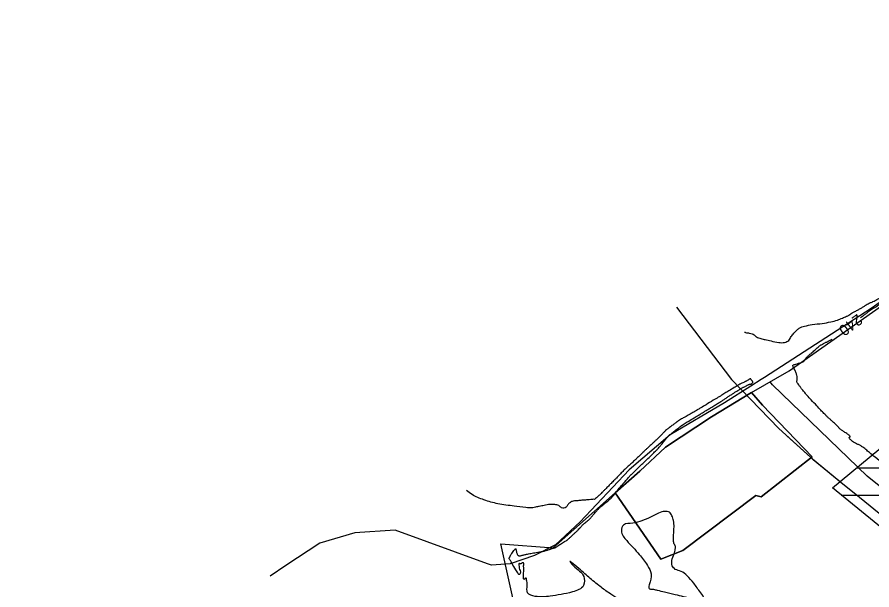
# Model space of a CAD drawing. Extents: x -478464 to -472469, y -1118040 to -1113785.
# Drawn here: x -477315.2 to -477003.6, y -1115098.1 to -1114889.2 of the extents above; entities that cross this region are included whole.
import ezdxf

# ---------------------------------------------------------------- set-up
doc = ezdxf.new("R2010")
doc.units = 0
for name, color, linetype in [('meliorace', 7, 'Continuous'), ('ObPÚ', 7, 'Continuous'), ('silnice', 7, 'Continuous'), ('telekomunikační kabel_O2', 7, 'Continuous'), ('vodní plochy', 7, 'Continuous'), ('Vrstevnice_hlavni', 7, 'Continuous'), ('Vrstevnice_popis', 7, 'Continuous'), ('Vrstevnice_vedlejsi', 7, 'Continuous')]:
    doc.layers.add(name, color=color, linetype=linetype)

msp = doc.modelspace()

# ---------------------------------------------------------------- linework, layer by layer
at = {"layer": 'meliorace'}
for p, q in [((-477009.054, -1115053.499), (-476582.646, -1115053.499)), ((-477014.727, -1115063.499), (-476601.498, -1115063.499))]:
    msp.add_line(p, q, dxfattribs=at)
for points in [[(-477017.961, -1115060.861), (-476936.974, -1114993.925), (-476875.969, -1114949.47), (-476746.767, -1114867.304), (-476662.849, -1114823.347), (-476637.541, -1114817.103), (-476620.225, -1114819.6), (-476613.565, -1114820.849), (-476597.581, -1114814.605), (-476585.593, -1114810.859), (-476574.669, -1114809.36), (-476544.304, -1114813.357), (-476526.985, -1114812.108), (-476492.353, -1114802.118), (-476476.377, -1114797.375), (-476438.008, -1114791.379), (-476414.829, -1114820.6), (-476383.929, -1114845.826), (-476320.786, -1114840.579)], [(-476300.545, -1114963.207), (-476368.477, -1114983.187), (-476385.793, -1114988.182), (-476407.105, -1114989.43), (-476428.417, -1114990.679), (-476466.247, -1114999.171), (-476589.855, -1115056.864), (-476650.329, -1115091.328), (-476713.19, -1115137.026), (-476738.506, -1115158.512), (-476785.126, -1115129.041), (-476863.979, -1115186.483), (-477017.961, -1115060.861)]]:
    msp.add_lwpolyline(points, dxfattribs=at)
at = {"layer": 'ObPÚ'}
for p, q in [((-477047.46, -1115026.08), (-477062.09, -1115034.97)), ((-477043.48, -1115030.71), (-477047.46, -1115026.08)), ((-477072.47, -1115083.76), (-477045.85, -1115063.61))]:
    msp.add_line(p, q, dxfattribs=at)
for points in [[(-477315.25, -1115330.18), (-477231.42, -1115250.62), (-477154.22, -1115173.58), (-477134.18, -1115148.75), (-477133.16, -1115130.26), (-477132.09, -1115111.94), (-477138.91, -1115081.32), (-477119.74, -1115082.72), (-477097.23, -1115062.71), (-477080.55, -1115086.81), (-477072.47, -1115083.76), (-477045.85, -1115063.61), (-477043.93, -1115064.09), (-477025.31, -1115049.55), (-477043.48, -1115030.71), (-477047.46, -1115026.08), (-477033.7, -1115018.17), (-476933.96, -1114947.92), (-476834.35, -1114877.76), (-476714.64, -1114803.8), (-476602.93, -1114745.91), (-476491.34, -1114705.52), (-476390.17, -1114678.77), (-476300.68, -1114655.71)], [(-477047.46, -1115026.08), (-477043.48, -1115030.71), (-477025.31, -1115049.55), (-477043.93, -1115064.09), (-477045.85, -1115063.61), (-477072.47, -1115083.76), (-477080.55, -1115086.81), (-477097.23, -1115062.71), (-477088.23, -1115054.79), (-477078.85, -1115045.98), (-477062.09, -1115034.97), (-477047.46, -1115026.08)], [(-477045.85, -1115063.61), (-477043.93, -1115064.09), (-477025.31, -1115049.55), (-477043.48, -1115030.71)], [(-477062.09, -1115034.97), (-477078.85, -1115045.98), (-477088.23, -1115054.79), (-477097.23, -1115062.71), (-477080.55, -1115086.81), (-477072.47, -1115083.76)]]:
    msp.add_lwpolyline(points, dxfattribs=at)
at = {"layer": 'silnice'}
msp.add_lwpolyline([(-476261.922, -1115907.288), (-476366.595, -1115823.727), (-476390.845, -1115803.24), (-476425.665, -1115718.481), (-476494.983, -1115557.356), (-476524.795, -1115496.42), (-476580.823, -1115418.032), (-476641.911, -1115352.297), (-476741.891, -1115268.259), (-476824.194, -1115202.313), (-477005.33, -1115056.573), (-477039.82, -1115023.276), (-477040.729, -1115022.048)], dxfattribs=at)
at = {"layer": 'telekomunikační kabel_O2'}
msp.add_line((-477011.16, -1115061.79), (-477010.07, -1115062.67), dxfattribs=at)
msp.add_line((-477011.16, -1115061.79), (-477010.07, -1115062.67), dxfattribs=at)
for points in [[(-477074.85, -1114994.92), (-477054.75, -1115021.38), (-477037.48, -1115039.27), (-477026.01, -1115049.69), (-477014.91, -1115058.73)], [(-477034.596, -1115041.89), (-477026.01, -1115049.69), (-477014.91, -1115058.73)], [(-477025.002, -1115050.511), (-477014.91, -1115058.73)], [(-477025.002, -1115050.511), (-477014.91, -1115058.73)], [(-477014.91, -1115058.73), (-477011.16, -1115061.79)], [(-477014.91, -1115058.73), (-477011.16, -1115061.79)], [(-477014.91, -1115058.73), (-477014.596, -1115058.986)], [(-477014.91, -1115058.73), (-477014.596, -1115058.986)], [(-477010.07, -1115062.67), (-476985.91, -1115082.25)]]:
    msp.add_lwpolyline(points, dxfattribs=at)
at = {"layer": 'vodní plochy'}
msp.add_lwpolyline([(-476969.074, -1114970.997), (-477003.853, -1114995.482), (-477042.717, -1115020.667), (-477043.996, -1115021.391), (-477047.718, -1115023.792), (-477057.356, -1115029.838), (-477077.169, -1115041.531), (-477092.092, -1115054.27), (-477110.002, -1115073.251), (-477118.905, -1115081.598), (-477126.545, -1115085.486), (-477135.508, -1115088.514), (-477142.313, -1115089.059), (-477143.75, -1115088.538), (-477177.386, -1115076.347), (-477192.107, -1115077.213), (-477204.809, -1115080.97), (-477217.213, -1115089.231), (-477222.967, -1115093.062)], dxfattribs=at)
at = {"layer": 'Vrstevnice_hlavni'}
for points in [[(-477049.979, -1115004.029), (-477049.673, -1115004.193), (-477048.26, -1115004.404), (-477047.204, -1115004.683), (-477046.505, -1115005.027), (-477046.164, -1115005.438), (-477045.639, -1115005.805), (-477044.929, -1115006.127), (-477044.034, -1115006.405), (-477042.508, -1115006.787), (-477040.351, -1115007.273), (-477037.562, -1115007.863), (-477035.407, -1115007.799), (-477033.886, -1115007.079), (-477033, -1115005.704), (-477032.062, -1115004.503), (-477031.073, -1115003.477), (-477030.034, -1115002.625), (-477028.119, -1115001.907), (-477025.328, -1115001.324), (-477021.663, -1115000.876), (-477018.599, -1115000.325), (-477016.138, -1114999.672), (-477014.278, -1114998.917), (-477012.873, -1114998.304), (-477011.923, -1114997.835), (-477011.428, -1114997.509), (-477010.705, -1114997.08), (-477009.754, -1114996.549), (-477008.574, -1114995.914), (-477007.491, -1114995.299), (-477006.505, -1114994.702), (-477005.616, -1114994.125), (-477004.874, -1114993.69), (-477004.28, -1114993.398), (-477003.833, -1114993.249), (-477003.188, -1114992.955), (-477002.345, -1114992.516), (-477001.305, -1114991.933), (-477000.403, -1114991.481), (-476999.64, -1114991.162), (-476999.016, -1114990.973), (-476998.464, -1114990.728), (-476997.985, -1114990.425), (-476997.579, -1114990.066), (-476997.143, -1114989.765), (-476996.676, -1114989.524), (-476996.178, -1114989.342), (-476995.627, -1114989.011), (-476995.023, -1114988.533), (-476994.365, -1114987.907), (-476993.741, -1114987.384), (-476993.153, -1114986.963), (-476992.599, -1114986.645), (-476992.009, -1114986.355), (-476991.383, -1114986.092), (-476990.719, -1114985.856), (-476990.255, -1114985.689), (-476989.991, -1114985.591), (-476989.925, -1114985.561), (-476989.901, -1114985.553), (-476989.919, -1114985.568), (-476989.977, -1114985.605), (-476990.02, -1114985.633), (-476990.048, -1114985.653), (-476990.061, -1114985.663), (-476990.326, -1114985.857), (-476990.841, -1114986.233), (-476991.608, -1114986.792), (-476992.308, -1114987.388), (-476992.94, -1114988.02), (-476993.504, -1114988.689), (-476994.025, -1114989.245), (-476994.503, -1114989.688), (-476994.937, -1114990.017), (-476995.402, -1114990.301), (-476995.899, -1114990.54), (-476996.428, -1114990.734), (-476996.92, -1114991.026), (-476997.375, -1114991.417), (-476997.795, -1114991.906), (-476998.298, -1114992.365), (-476998.884, -1114992.793), (-476999.553, -1114993.19), (-477000.214, -1114993.61), (-477000.867, -1114994.052), (-477001.512, -1114994.518), (-477002.106, -1114994.907), (-477002.649, -1114995.22), (-477003.142, -1114995.458), (-477003.814, -1114995.885), (-477004.665, -1114996.502)], [(-477004.665, -1114996.502), (-477005.695, -1114997.309), (-477006.489, -1114997.933), (-477007.047, -1114998.372), (-477007.691, -1114998.882)], [(-477017.894, -1115036.673), (-477018.831, -1115035.848), (-477019.673, -1115035.079), (-477020.422, -1115034.367), (-477021.076, -1115033.712), (-477022.168, -1115032.564), (-477023.697, -1115030.923), (-477025.662, -1115028.788), (-477027.122, -1115027.188), (-477028.074, -1115026.123), (-477028.52, -1115025.593), (-477029.034, -1115024.943), (-477029.617, -1115024.173), (-477030.269, -1115023.282), (-477030.708, -1115022.682), (-477030.934, -1115022.374), (-477030.946, -1115022.357), (-477030.928, -1115022.077), (-477030.878, -1115021.535), (-477030.797, -1115020.729), (-477030.934, -1115019.788), (-477031.286, -1115018.713), (-477031.856, -1115017.503), (-477032.238, -1115016.683), (-477032.433, -1115016.253), (-477032.44, -1115016.214), (-477032.443, -1115016.185), (-477032.441, -1115016.166), (-477032.435, -1115016.159), (-477032.431, -1115016.153), (-477032.428, -1115016.149), (-477032.426, -1115016.147), (-477032.373, -1115016.122), (-477032.267, -1115016.074), (-477032.11, -1115016.003), (-477031.64, -1115015.843), (-477030.858, -1115015.596), (-477029.763, -1115015.26), (-477028.959, -1115014.975), (-477028.444, -1115014.74), (-477028.219, -1115014.556), (-477028.06, -1115014.364), (-477027.968, -1115014.165), (-477027.943, -1115013.958), (-477027.674, -1115013.593), (-477027.161, -1115013.071), (-477026.405, -1115012.392), (-477025.889, -1115011.927), (-477025.616, -1115011.677), (-477025.583, -1115011.642), (-477025.534, -1115011.602), (-477025.469, -1115011.556), (-477025.387, -1115011.505), (-477025.033, -1115011.201), (-477024.407, -1115010.643), (-477023.509, -1115009.833), (-477022.858, -1115009.263), (-477022.455, -1115008.935), (-477022.299, -1115008.848), (-477021.991, -1115008.674), (-477021.533, -1115008.413), (-477020.923, -1115008.064), (-477020.468, -1115007.826), (-477020.167, -1115007.697), (-477020.021, -1115007.678), (-477019.883, -1115007.635), (-477019.754, -1115007.567), (-477019.633, -1115007.475), (-477019.398, -1115007.325), (-477019.047, -1115007.117), (-477018.115, -1115006.584)], [(-476873.251, -1115143.677), (-476873.507, -1115142.01), (-476873.554, -1115139.102), (-476873.522, -1115134.12), (-476873.41, -1115127.063), (-476873.808, -1115122.086), (-476874.717, -1115119.19), (-476876.136, -1115118.374), (-476877.354, -1115117.171), (-476878.371, -1115115.579), (-476879.185, -1115113.6), (-476882.364, -1115111.475), (-476887.908, -1115109.205), (-476895.815, -1115106.789), (-476902.242, -1115103.761), (-476907.186, -1115100.12), (-476910.649, -1115095.867), (-476913.66, -1115091.883), (-476916.218, -1115088.167), (-476918.324, -1115084.72), (-476919.725, -1115082.379), (-476920.421, -1115081.145), (-476920.412, -1115081.017), (-476920.426, -1115080.932), (-476920.462, -1115080.891), (-476920.521, -1115080.893), (-476920.576, -1115080.895), (-476920.627, -1115080.896), (-476920.674, -1115080.898), (-476921.736, -1115080.799), (-476923.814, -1115080.599), (-476926.907, -1115080.3), (-476932.302, -1115079.591), (-476940, -1115078.472), (-476950, -1115076.944), (-476957.876, -1115075.006), (-476963.629, -1115072.657), (-476967.259, -1115069.897), (-476970.802, -1115067.892), (-476974.259, -1115066.643), (-476977.631, -1115066.149), (-476980.601, -1115065.341), (-476983.17, -1115064.218), (-476985.338, -1115062.781), (-476986.878, -1115061.747), (-476987.79, -1115061.118), (-476988.074, -1115060.892), (-476988.478, -1115060.587), (-476989.003, -1115060.204), (-476989.648, -1115059.743), (-476990.332, -1115059.246), (-476991.055, -1115058.714), (-476991.817, -1115058.146), (-476992.891, -1115057.395), (-476994.277, -1115056.46), (-476995.976, -1115055.343), (-476997.039, -1115054.593), (-476997.464, -1115054.21), (-476997.254, -1115054.195), (-476998.009, -1115053.437), (-476999.729, -1115051.937), (-477002.416, -1115049.693), (-477004.444, -1115048.001), (-477005.814, -1115046.86), (-477006.527, -1115046.27), (-477007.324, -1115045.723), (-477008.206, -1115045.221), (-477009.173, -1115044.763), (-477009.833, -1115044.445), (-477010.186, -1115044.267), (-477010.232, -1115044.228), (-477010.318, -1115044.158), (-477010.443, -1115044.058), (-477010.608, -1115043.927), (-477010.866, -1115043.703), (-477011.219, -1115043.389), (-477011.666, -1115042.982), (-477011.859, -1115042.654), (-477011.796, -1115042.405), (-477011.479, -1115042.235), (-477011.695, -1115041.846), (-477012.445, -1115041.236), (-477013.729, -1115040.407), (-477014.642, -1115039.799), (-477015.184, -1115039.41), (-477015.355, -1115039.241), (-477015.476, -1115039.117), (-477015.545, -1115039.038), (-477015.564, -1115039.003), (-477015.672, -1115038.875), (-477015.869, -1115038.653), (-477016.157, -1115038.339), (-477016.405, -1115038.07), (-477016.615, -1115037.849), (-477016.786, -1115037.674), (-477017.213, -1115037.282), (-477017.894, -1115036.673)]]:
    msp.add_spline(points, degree=3, dxfattribs=at)
at = {"layer": 'Vrstevnice_vedlejsi'}
for points in [[(-477108.024, -1115073.453), (-477107.41, -1115072.982), (-477106.961, -1115072.629), (-477106.676, -1115072.395), (-477106.556, -1115072.278), (-477106.091, -1115071.757), (-477105.281, -1115070.832), (-477104.126, -1115069.502), (-477103.309, -1115068.574), (-477102.828, -1115068.046), (-477102.685, -1115067.92), (-477102.316, -1115067.626), (-477101.72, -1115067.165), (-477100.898, -1115066.537), (-477100.184, -1115065.97), (-477099.579, -1115065.464), (-477099.081, -1115065.02), (-477098.73, -1115064.701), (-477098.524, -1115064.509), (-477098.465, -1115064.444), (-477098.01, -1115063.889), (-477097.162, -1115062.844), (-477095.919, -1115061.311), (-477094.978, -1115060.158), (-477094.339, -1115059.385), (-477094.002, -1115058.992), (-477093.57, -1115058.494), (-477093.044, -1115057.889), (-477092.423, -1115057.178), (-477091.967, -1115056.663), (-477091.675, -1115056.343), (-477091.547, -1115056.218), (-477091.414, -1115056.093), (-477091.276, -1115055.968), (-477091.133, -1115055.843), (-477090.09, -1115054.841), (-477088.145, -1115052.963), (-477085.299, -1115050.207), (-477083.328, -1115048.299), (-477082.232, -1115047.238), (-477082.012, -1115047.025), (-477081.803, -1115046.81), (-477081.606, -1115046.593), (-477081.422, -1115046.376), (-477080.916, -1115045.76), (-477080.09, -1115044.745), (-477078.942, -1115043.332), (-477078.165, -1115042.381), (-477077.759, -1115041.889), (-477077.722, -1115041.859), (-477077.193, -1115041.444), (-477076.171, -1115040.644), (-477074.656, -1115039.459), (-477073.586, -1115038.623), (-477072.96, -1115038.136), (-477072.779, -1115037.999), (-477071.961, -1115037.49), (-477070.508, -1115036.61), (-477068.419, -1115035.359), (-477066.799, -1115034.381), (-477065.649, -1115033.675), (-477064.968, -1115033.243), (-477064.004, -1115032.647), (-477062.756, -1115031.889), (-477061.226, -1115030.967), (-477059.874, -1115030.136), (-477058.7, -1115029.396), (-477057.706, -1115028.747), (-477056.705, -1115028.092), (-477055.698, -1115027.432), (-477054.685, -1115026.767), (-477053.73, -1115026.157), (-477052.836, -1115025.601), (-477052, -1115025.101), (-477051.326, -1115024.7), (-477050.814, -1115024.399), (-477050.463, -1115024.197), (-477050.058, -1115023.975), (-477049.6, -1115023.733), (-477049.089, -1115023.47), (-477048.739, -1115023.29), (-477048.551, -1115023.192), (-477048.525, -1115023.177), (-477048.392, -1115023.144), (-477048.151, -1115023.091), (-477047.802, -1115023.02), (-477047.557, -1115022.962), (-477047.416, -1115022.917), (-477047.38, -1115022.886), (-477047.304, -1115022.801), (-477047.188, -1115022.663), (-477047.034, -1115022.472), (-477047.024, -1115022.224), (-477047.159, -1115021.92), (-477047.44, -1115021.559), (-477047.642, -1115021.3), (-477047.764, -1115021.143)], [(-477047.764, -1115021.143), (-477047.807, -1115021.087), (-477047.84, -1115021.051), (-477047.862, -1115021.035), (-477047.874, -1115021.038), (-477048.066, -1115021.148), (-477048.439, -1115021.365), (-477048.993, -1115021.689), (-477049.369, -1115021.906), (-477049.566, -1115022.018), (-477049.585, -1115022.024), (-477049.603, -1115022.032), (-477049.62, -1115022.044), (-477049.636, -1115022.059), (-477049.869, -1115022.179), (-477050.319, -1115022.405), (-477050.986, -1115022.735), (-477051.44, -1115022.961), (-477051.68, -1115023.08), (-477051.707, -1115023.094), (-477052.394, -1115023.504), (-477053.742, -1115024.308), (-477055.751, -1115025.507), (-477057.143, -1115026.339), (-477057.916, -1115026.803), (-477058.072, -1115026.899), (-477058.233, -1115027.001), (-477058.398, -1115027.108), (-477058.569, -1115027.221), (-477059.569, -1115027.831), (-477061.399, -1115028.936), (-477064.059, -1115030.537), (-477065.922, -1115031.657), (-477066.987, -1115032.295), (-477067.255, -1115032.451), (-477067.533, -1115032.618), (-477067.822, -1115032.796), (-477068.122, -1115032.984), (-477068.88, -1115033.421), (-477070.096, -1115034.105), (-477071.77, -1115035.038), (-477072.989, -1115035.726), (-477073.751, -1115036.168), (-477074.057, -1115036.365), (-477074.333, -1115036.554), (-477074.579, -1115036.736), (-477074.794, -1115036.91), (-477075.324, -1115037.31), (-477076.168, -1115037.936), (-477077.327, -1115038.79), (-477078.203, -1115039.464), (-477078.798, -1115039.959), (-477079.111, -1115040.275), (-477079.455, -1115040.634), (-477079.831, -1115041.038), (-477080.238, -1115041.485), (-477080.787, -1115042.043), (-477081.476, -1115042.712), (-477082.307, -1115043.493), (-477083.019, -1115044.159), (-477083.61, -1115044.71), (-477084.082, -1115045.147), (-477084.651, -1115045.674), (-477085.315, -1115046.29), (-477086.075, -1115046.995), (-477086.782, -1115047.662), (-477087.437, -1115048.292), (-477088.038, -1115048.885), (-477088.682, -1115049.509), (-477089.369, -1115050.164), (-477090.097, -1115050.851), (-477090.791, -1115051.495), (-477091.451, -1115052.094), (-477092.076, -1115052.649), (-477092.683, -1115053.204), (-477093.273, -1115053.758), (-477093.846, -1115054.312), (-477094.405, -1115054.864), (-477094.949, -1115055.416), (-477095.479, -1115055.966), (-477096.073, -1115056.582), (-477096.731, -1115057.264), (-477097.453, -1115058.011), (-477098.084, -1115058.661), (-477098.627, -1115059.215), (-477099.079, -1115059.673), (-477099.591, -1115060.191), (-477100.163, -1115060.77), (-477100.794, -1115061.411), (-477101.243, -1115061.866), (-477101.509, -1115062.137), (-477101.593, -1115062.222), (-477101.981, -1115062.587), (-477102.673, -1115063.234), (-477103.67, -1115064.162), (-477104.352, -1115064.774), (-477104.719, -1115065.07)], [(-477104.719, -1115065.07), (-477104.772, -1115065.05), (-477105.421, -1115065.088), (-477106.667, -1115065.183), (-477108.511, -1115065.336), (-477110.106, -1115065.477), (-477111.454, -1115065.605), (-477112.553, -1115065.721), (-477113.519, -1115066.142), (-477114.351, -1115066.867), (-477115.049, -1115067.896), (-477115.853, -1115068.319), (-477116.761, -1115068.135), (-477117.775, -1115067.344), (-477119.166, -1115066.938), (-477120.933, -1115066.918), (-477123.077, -1115067.283), (-477124.834, -1115067.608), (-477126.206, -1115067.891), (-477127.191, -1115068.133), (-477129.805, -1115068.007), (-477134.047, -1115067.513), (-477139.917, -1115066.65), (-477145.027, -1115065.24), (-477149.376, -1115063.284), (-477151.42, -1115061.854)], [(-477084.767, -1115096.166), (-477084.101, -1115092.168), (-477085.414, -1115089.159), (-477088.375, -1115085.141), (-477092.982, -1115080.113), (-477094.907, -1115076.543), (-477094.15, -1115074.431), (-477090.711, -1115073.778), (-477087.427, -1115072.83), (-477084.299, -1115071.587), (-477081.325, -1115070.05), (-477079.03, -1115069.446), (-477077.412, -1115069.774), (-477076.472, -1115071.036), (-477075.902, -1115072.82), (-477075.702, -1115075.127), (-477075.871, -1115077.957), (-477075.854, -1115080.036), (-477075.649, -1115081.363), (-477075.256, -1115081.94), (-477075.268, -1115083.139), (-477075.685, -1115084.961), (-477076.505, -1115087.406), (-477076.358, -1115089.277), (-477075.242, -1115090.575), (-477073.158, -1115091.299), (-477070.923, -1115092.964), (-477068.536, -1115095.569), (-477065.998, -1115099.114), (-477064.928, -1115101.316), (-477065.326, -1115102.175), (-477067.193, -1115101.689), (-477068.694, -1115101.308), (-477069.828, -1115101.031), (-477070.596, -1115100.857), (-477072.409, -1115100.429), (-477075.269, -1115099.746), (-477079.173, -1115098.808), (-477081.829, -1115098.176), (-477083.236, -1115097.849), (-477083.394, -1115097.828), (-477083.654, -1115097.801), (-477084.015, -1115097.767), (-477084.479, -1115097.728), (-477084.768, -1115097.532), (-477084.883, -1115097.181), (-477084.767, -1115096.166)], [(-477129.643, -1115093.662), (-477129.855, -1115093.807), (-477130.059, -1115093.953), (-477130.255, -1115094.099), (-477130.445, -1115094.246), (-477130.55, -1115093.657), (-477130.571, -1115092.334), (-477130.508, -1115090.275), (-477130.534, -1115088.901), (-477130.65, -1115088.214), (-477130.857, -1115088.211), (-477131.052, -1115088.259), (-477131.235, -1115088.355), (-477131.407, -1115088.501), (-477131.624, -1115088.556), (-477131.885, -1115088.52), (-477132.189, -1115088.393), (-477132.278, -1115088.939), (-477132.151, -1115090.158), (-477131.807, -1115092.05), (-477132.073, -1115092.497), (-477132.948, -1115091.498), (-477134.433, -1115089.053), (-477135.392, -1115087.379), (-477135.824, -1115086.476), (-477135.732, -1115086.343), (-477135.622, -1115086.14), (-477135.496, -1115085.867), (-477135.352, -1115085.524), (-477135.069, -1115085.043), (-477134.645, -1115084.425), (-477134.081, -1115083.669), (-477133.693, -1115083.193), (-477133.481, -1115082.995), (-477133.446, -1115083.075), (-477133.419, -1115083.139), (-477133.4, -1115083.187), (-477133.39, -1115083.217), (-477133.336, -1115083.429), (-477133.239, -1115083.824), (-477133.098, -1115084.4), (-477132.937, -1115084.867), (-477132.754, -1115085.224), (-477132.55, -1115085.472), (-477132.273, -1115085.607), (-477131.924, -1115085.629), (-477131.503, -1115085.538), (-477131.093, -1115085.446), (-477130.693, -1115085.354), (-477130.303, -1115085.261), (-477129.783, -1115085.141), (-477129.131, -1115084.995), (-477128.35, -1115084.823), (-477127.47, -1115084.655), (-477126.491, -1115084.493), (-477125.414, -1115084.335), (-477124.621, -1115084.217), (-477124.114, -1115084.138), (-477123.891, -1115084.098), (-477123.449, -1115083.985), (-477122.787, -1115083.8), (-477121.905, -1115083.541), (-477121.265, -1115083.345), (-477120.867, -1115083.213), (-477120.711, -1115083.143), (-477120.481, -1115083.058), (-477120.176, -1115082.956), (-477119.798, -1115082.837), (-477119.534, -1115082.756), (-477119.385, -1115082.712), (-477119.35, -1115082.705), (-477119.288, -1115082.693), (-477119.198, -1115082.677), (-477119.082, -1115082.657), (-477119.001, -1115082.642), (-477118.957, -1115082.632), (-477118.949, -1115082.628), (-477118.741, -1115082.484), (-477118.333, -1115082.199), (-477117.725, -1115081.775), (-477117.071, -1115081.344), (-477116.374, -1115080.908), (-477115.631, -1115080.466), (-477115.101, -1115080.147), (-477114.783, -1115079.952), (-477114.678, -1115079.88), (-477114.253, -1115079.504), (-477113.508, -1115078.823), (-477112.443, -1115077.838), (-477111.674, -1115077.129), (-477111.202, -1115076.694), (-477111.026, -1115076.535), (-477110.663, -1115076.156), (-477110.113, -1115075.558), (-477109.375, -1115074.741), (-477108.679, -1115074.039), (-477108.024, -1115073.453)], [(-477145.994, -1115130.93), (-477145.907, -1115130.949), (-477145.792, -1115130.975), (-477145.65, -1115131.008), (-477145.481, -1115131.047), (-477145.355, -1115131.153), (-477145.271, -1115131.326), (-477145.229, -1115131.567), (-477145.169, -1115131.745), (-477145.091, -1115131.861), (-477144.995, -1115131.914), (-477144.768, -1115132.33), (-477144.41, -1115133.109), (-477143.921, -1115134.25), (-477143.473, -1115135.123), (-477143.067, -1115135.728), (-477142.703, -1115136.064), (-477142.298, -1115136.403), (-477141.851, -1115136.742), (-477141.362, -1115137.084), (-477140.677, -1115137.524), (-477139.796, -1115138.061), (-477138.718, -1115138.696), (-477137.989, -1115139.121), (-477137.608, -1115139.337), (-477137.576, -1115139.344), (-477137.371, -1115138.849), (-477136.992, -1115137.853), (-477136.441, -1115136.356), (-477135.916, -1115135.328), (-477135.418, -1115134.771), (-477134.946, -1115134.683), (-477134.587, -1115134.579), (-477134.341, -1115134.46), (-477134.209, -1115134.324), (-477133.319, -1115134.179), (-477131.672, -1115134.026), (-477129.269, -1115133.863), (-477128.244, -1115133.003), (-477128.597, -1115131.444), (-477130.328, -1115129.187), (-477130.863, -1115127.236), (-477130.202, -1115125.591), (-477128.344, -1115124.252), (-477126.5, -1115123.02), (-477124.668, -1115121.895), (-477122.85, -1115120.877), (-477121.643, -1115120.158), (-477121.049, -1115119.737), (-477121.066, -1115119.615), (-477121.462, -1115119.154), (-477122.237, -1115118.356), (-477123.39, -1115117.219), (-477124.078, -1115116.277), (-477124.301, -1115115.53), (-477124.06, -1115114.978), (-477124.281, -1115113.735), (-477124.966, -1115111.8), (-477126.113, -1115109.174), (-477123.549, -1115107.946), (-477117.274, -1115108.116), (-477107.287, -1115109.684), (-477100.243, -1115110.346), (-477096.142, -1115110.101), (-477094.985, -1115108.95), (-477094.099, -1115108.048), (-477093.486, -1115107.396), (-477093.145, -1115106.994), (-477092.79, -1115106.515), (-477092.422, -1115105.958), (-477092.04, -1115105.325), (-477091.701, -1115104.783), (-477091.403, -1115104.332), (-477091.147, -1115103.973), (-477091.418, -1115103.476), (-477092.215, -1115102.842), (-477093.538, -1115102.069), (-477094.274, -1115101.745), (-477094.421, -1115101.87), (-477093.98, -1115102.444), (-477094.699, -1115102.169), (-477096.577, -1115101.045), (-477099.615, -1115099.073), (-477103.181, -1115096.412), (-477107.275, -1115093.063), (-477111.897, -1115089.024), (-477113.665, -1115087.698), (-477112.579, -1115089.085), (-477108.64, -1115093.184), (-477108.708, -1115096.426), (-477112.784, -1115098.812), (-477120.869, -1115100.342), (-477126.312, -1115100.433), (-477129.113, -1115099.086), (-477129.272, -1115096.301), (-477129.449, -1115094.493), (-477129.643, -1115093.662)]]:
    msp.add_spline(points, degree=3, dxfattribs=at)

# ---------------------------------------------------------------- texts
at = {"layer": 'Vrstevnice_popis'}
msp.add_text(' 240 ', height=4, rotation=216.46088, dxfattribs=at).set_placement((-477007.655, -1114996.369))

doc.saveas('drawing.dxf')
